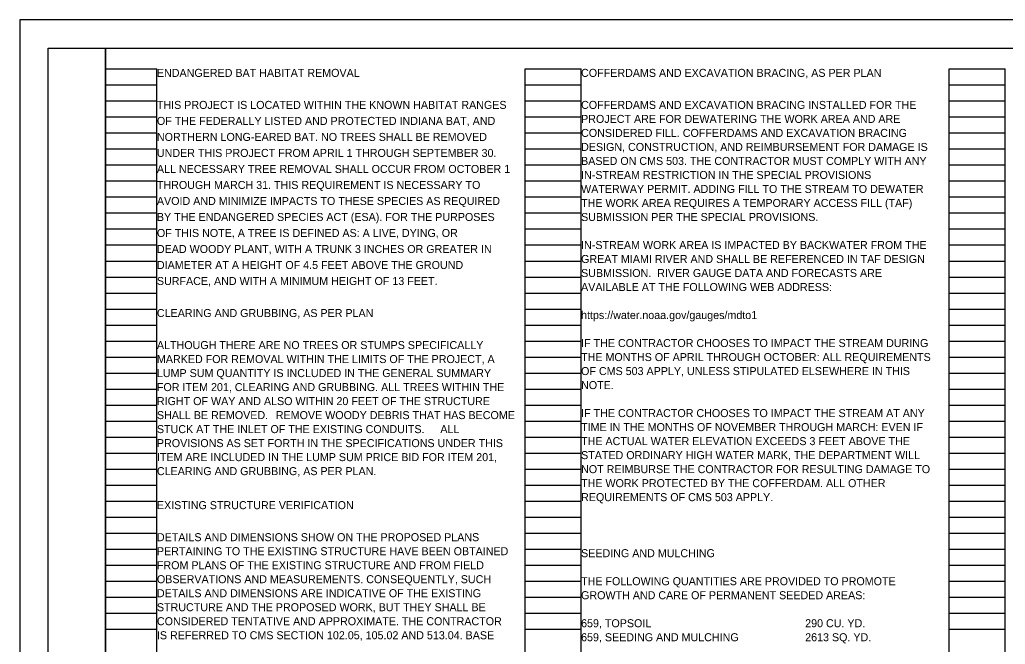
# Model space of a CAD drawing. Extents: x 0 to 34, y 0 to 41.9.
# Drawn here: x 0 to 17.24, y 11.08 to 22 of the extents above; entities that cross this region are included whole.
import ezdxf

# ---------------------------------------------------------------- set-up
doc = ezdxf.new("R2010")
doc.units = 0
for name, color, linetype in [('SH_Border', 7, 'Continuous'), ('SH_Cut_Line', 7, 'Continuous'), ('SH_Data', 7, 'Continuous'), ('SH_Text', 7, 'Continuous')]:
    doc.layers.add(name, color=color, linetype=linetype)

msp = doc.modelspace()

# ---------------------------------------------------------------- linework, layer by layer
at = {"layer": 'SH_Border'}
for points in [[(0.5, 21.5), (1.5, 21.5), (1.5, 0.5), (0.5, 0.5)], [(1.5, 21.5), (33.5, 21.5), (33.5, 0.5), (1.5, 0.5)]]:
    msp.add_lwpolyline(points, close=True, dxfattribs=at)
at = {"layer": 'SH_Cut_Line'}
msp.add_lwpolyline([(0, 0), (34, 0), (34, 22), (0, 22)], close=True, dxfattribs=at)
at = {"layer": 'SH_Data'}
for p, q in [((1.5, 0.98), (1.5, 21.14)), ((1.5, 21.14), (2.4, 21.14)), ((2.4, 0.98), (2.4, 21.14)), ((8.84, 0.98), (8.84, 21.14)), ((8.84, 21.14), (9.82, 21.14)), ((9.82, 0.98), (9.82, 21.14)), ((16.26, 0.98), (16.26, 21.14)), ((16.26, 21.14), (17.24, 21.14)), ((17.24, 0.98), (17.24, 21.14)), ((1.5, 20.86), (2.4, 20.86)), ((8.84, 20.86), (9.82, 20.86)), ((16.26, 20.86), (17.24, 20.86)), ((1.5, 20.58), (2.4, 20.58)), ((8.84, 20.58), (9.82, 20.58)), ((16.26, 20.58), (17.24, 20.58)), ((1.5, 20.3), (2.4, 20.3)), ((8.84, 20.3), (9.82, 20.3)), ((16.26, 20.3), (17.24, 20.3)), ((1.5, 20.02), (2.4, 20.02)), ((8.84, 20.02), (9.82, 20.02)), ((16.26, 20.02), (17.24, 20.02)), ((1.5, 19.74), (2.4, 19.74)), ((8.84, 19.74), (9.82, 19.74)), ((16.26, 19.74), (17.24, 19.74)), ((1.5, 19.46), (2.4, 19.46)), ((8.84, 19.46), (9.82, 19.46)), ((16.26, 19.46), (17.24, 19.46)), ((1.5, 19.18), (2.4, 19.18)), ((8.84, 19.18), (9.82, 19.18)), ((16.26, 19.18), (17.24, 19.18)), ((1.5, 18.9), (2.4, 18.9)), ((8.84, 18.9), (9.82, 18.9)), ((16.26, 18.9), (17.24, 18.9)), ((1.5, 18.62), (2.4, 18.62)), ((8.84, 18.62), (9.82, 18.62)), ((16.26, 18.62), (17.24, 18.62)), ((1.5, 18.34), (2.4, 18.34)), ((8.84, 18.34), (9.82, 18.34)), ((16.26, 18.34), (17.24, 18.34)), ((1.5, 18.06), (2.4, 18.06)), ((8.84, 18.06), (9.82, 18.06)), ((16.26, 18.06), (17.24, 18.06)), ((1.5, 17.78), (2.4, 17.78)), ((8.84, 17.78), (9.82, 17.78)), ((16.26, 17.78), (17.24, 17.78)), ((1.5, 17.5), (2.4, 17.5)), ((8.84, 17.5), (9.82, 17.5)), ((16.26, 17.5), (17.24, 17.5)), ((1.5, 17.22), (2.4, 17.22)), ((8.84, 17.22), (9.82, 17.22)), ((16.26, 17.22), (17.24, 17.22)), ((1.5, 16.94), (2.4, 16.94)), ((8.84, 16.94), (9.82, 16.94)), ((16.26, 16.94), (17.24, 16.94)), ((1.5, 16.66), (2.4, 16.66)), ((8.84, 16.66), (9.82, 16.66)), ((16.26, 16.66), (17.24, 16.66)), ((1.5, 16.38), (2.4, 16.38)), ((8.84, 16.38), (9.82, 16.38)), ((16.26, 16.38), (17.24, 16.38)), ((1.5, 16.1), (2.4, 16.1)), ((8.84, 16.1), (9.82, 16.1)), ((16.26, 16.1), (17.24, 16.1)), ((1.5, 15.82), (2.4, 15.82)), ((8.84, 15.82), (9.82, 15.82)), ((16.26, 15.82), (17.24, 15.82)), ((1.5, 15.54), (2.4, 15.54)), ((8.84, 15.54), (9.82, 15.54)), ((16.26, 15.54), (17.24, 15.54)), ((1.5, 15.26), (2.4, 15.26)), ((8.84, 15.26), (9.82, 15.26)), ((16.26, 15.26), (17.24, 15.26)), ((1.5, 14.98), (2.4, 14.98)), ((8.84, 14.98), (9.82, 14.98)), ((16.26, 14.98), (17.24, 14.98)), ((1.5, 14.7), (2.4, 14.7)), ((8.84, 14.7), (9.82, 14.7)), ((16.26, 14.7), (17.24, 14.7)), ((1.5, 14.42), (2.4, 14.42)), ((8.84, 14.42), (9.82, 14.42)), ((16.26, 14.42), (17.24, 14.42)), ((1.5, 14.14), (2.4, 14.14)), ((8.84, 14.14), (9.82, 14.14)), ((16.26, 14.14), (17.24, 14.14)), ((1.5, 13.86), (2.4, 13.86)), ((8.84, 13.86), (9.82, 13.86)), ((16.26, 13.86), (17.24, 13.86)), ((1.5, 13.58), (2.4, 13.58)), ((8.84, 13.58), (9.82, 13.58)), ((16.26, 13.58), (17.24, 13.58)), ((1.5, 13.3), (2.4, 13.3)), ((8.84, 13.3), (9.82, 13.3)), ((16.26, 13.3), (17.24, 13.3)), ((1.5, 13.02), (2.4, 13.02)), ((8.84, 13.02), (9.82, 13.02)), ((16.26, 13.02), (17.24, 13.02)), ((1.5, 12.74), (2.4, 12.74)), ((8.84, 12.74), (9.82, 12.74)), ((16.26, 12.74), (17.24, 12.74)), ((1.5, 12.46), (2.4, 12.46)), ((8.84, 12.46), (9.82, 12.46)), ((16.26, 12.46), (17.24, 12.46)), ((1.5, 12.18), (2.4, 12.18)), ((8.84, 12.18), (9.82, 12.18)), ((16.26, 12.18), (17.24, 12.18)), ((1.5, 11.9), (2.4, 11.9)), ((8.84, 11.9), (9.82, 11.9)), ((16.26, 11.9), (17.24, 11.9)), ((1.5, 11.62), (2.4, 11.62)), ((8.84, 11.62), (9.82, 11.62)), ((16.26, 11.62), (17.24, 11.62)), ((1.5, 11.34), (2.4, 11.34)), ((8.84, 11.34), (9.82, 11.34)), ((16.26, 11.34), (17.24, 11.34))]:
    msp.add_line(p, q, dxfattribs=at)

# ---------------------------------------------------------------- texts
at = {"layer": 'SH_Text'}
for s, p in [('ENDANGERED BAT HABITAT REMOVAL', (2.4, 21)), ('COFFERDAMS AND EXCAVATION BRACING, AS PER PLAN', (9.82, 21)), ('THIS PROJECT IS LOCATED WITHIN THE KNOWN HABITAT RANGES', (2.4, 20.44)), ('COFFERDAMS AND EXCAVATION BRACING INSTALLED FOR THE ', (9.82, 20.44)), ('OF THE FEDERALLY LISTED AND PROTECTED INDIANA BAT, AND', (2.4, 20.16)), ('PROJECT ARE FOR DEWATERING THE WORK AREA AND ARE ', (9.82, 20.195)), ('NORTHERN LONG-EARED BAT. NO TREES SHALL BE REMOVED', (2.4, 19.88)), ('CONSIDERED FILL. COFFERDAMS AND EXCAVATION BRACING ', (9.82, 19.95)), ('DESIGN, CONSTRUCTION, AND REIMBURSEMENT FOR DAMAGE IS ', (9.82, 19.705)), ('UNDER THIS PROJECT FROM APRIL 1 THROUGH SEPTEMBER 30.', (2.4, 19.6)), ('BASED ON CMS 503. THE CONTRACTOR MUST COMPLY WITH ANY ', (9.82, 19.46)), ('ALL NECESSARY TREE REMOVAL SHALL OCCUR FROM OCTOBER 1', (2.4, 19.32)), ('IN-STREAM RESTRICTION IN THE SPECIAL PROVISIONS  ', (9.82, 19.215)), ('THROUGH MARCH 31. THIS REQUIREMENT IS NECESSARY TO', (2.4, 19.04)), ('WATERWAY PERMIT. ADDING FILL TO THE STREAM TO DEWATER ', (9.82, 18.97)), ('AVOID AND MINIMIZE IMPACTS TO THESE SPECIES AS REQUIRED', (2.4, 18.76)), ('THE WORK AREA REQUIRES A TEMPORARY ACCESS FILL (TAF) ', (9.82, 18.725)), ('BY THE ENDANGERED SPECIES ACT (ESA). FOR THE PURPOSES', (2.4, 18.48)), ('SUBMISSION PER THE SPECIAL PROVISIONS. ', (9.82, 18.48)), ('OF THIS NOTE, A TREE IS DEFINED AS: A LIVE, DYING, OR', (2.4, 18.2)), ('IN-STREAM WORK AREA IS IMPACTED BY BACKWATER FROM THE ', (9.82, 17.99)), ('DEAD WOODY PLANT, WITH A TRUNK 3 INCHES OR GREATER IN', (2.4, 17.92)), ('DIAMETER AT A HEIGHT OF 4.5 FEET ABOVE THE GROUND', (2.4, 17.64)), ('GREAT MIAMI RIVER AND SHALL BE REFERENCED IN TAF DESIGN ', (9.82, 17.745)), ('SUBMISSION.  RIVER GAUGE DATA AND FORECASTS ARE ', (9.82, 17.5)), ('SURFACE, AND WITH A MINIMUM HEIGHT OF 13 FEET.', (2.4, 17.36)), ('AVAILABLE AT THE FOLLOWING WEB ADDRESS:', (9.82, 17.255)), ('CLEARING AND GRUBBING, AS PER PLAN', (2.4, 16.8)), ('https://water.noaa.gov/gauges/mdto1', (9.82, 16.765)), ('ALTHOUGH THERE ARE NO TREES OR STUMPS SPECIFICALLY ', (2.4, 16.24)), ('IF THE CONTRACTOR CHOOSES TO IMPACT THE STREAM DURING ', (9.82, 16.275)), ('MARKED FOR REMOVAL WITHIN THE LIMITS OF THE PROJECT, A ', (2.4, 15.995)), ('THE MONTHS OF APRIL THROUGH OCTOBER: ALL REQUIREMENTS ', (9.82, 16.03)), ('LUMP SUM QUANTITY IS INCLUDED IN THE GENERAL SUMMARY ', (2.4, 15.75)), ('OF CMS 503 APPLY, UNLESS STIPULATED ELSEWHERE IN THIS ', (9.82, 15.785)), ('FOR ITEM 201, CLEARING AND GRUBBING. ALL TREES WITHIN THE ', (2.4, 15.505)), ('NOTE.', (9.82, 15.54)), ('RIGHT OF WAY AND ALSO WITHIN 20 FEET OF THE STRUCTURE ', (2.4, 15.26)), ('IF THE CONTRACTOR CHOOSES TO IMPACT THE STREAM AT ANY ', (9.82, 15.05)), ('SHALL BE REMOVED. ', (2.4, 15.015)), ('REMOVE WOODY DEBRIS THAT HAS BECOME ', (4.48, 15.015)), ('STUCK AT THE INLET OF THE EXISTING CONDUITS. ', (2.4, 14.77)), (' ALL ', (7.306, 14.77)), ('TIME IN THE MONTHS OF NOVEMBER THROUGH MARCH: EVEN IF ', (9.82, 14.805)), ('PROVISIONS AS SET FORTH IN THE SPECIFICATIONS UNDER THIS ', (2.4, 14.525)), ('THE ACTUAL WATER ELEVATION EXCEEDS 3 FEET ABOVE THE ', (9.82, 14.56)), ('ITEM ARE INCLUDED IN THE LUMP SUM PRICE BID FOR ITEM 201, ', (2.4, 14.28)), ('STATED ORDINARY HIGH WATER MARK, THE DEPARTMENT WILL ', (9.82, 14.315)), ('CLEARING AND GRUBBING, AS PER PLAN.', (2.4, 14.035)), ('NOT REIMBURSE THE CONTRACTOR FOR RESULTING DAMAGE TO ', (9.82, 14.07)), ('THE WORK PROTECTED BY THE COFFERDAM. ALL OTHER ', (9.82, 13.825)), ('REQUIREMENTS OF CMS 503 APPLY.', (9.82, 13.58)), ('EXISTING STRUCTURE VERIFICATION', (2.4, 13.44)), ('DETAILS AND DIMENSIONS SHOW ON THE PROPOSED PLANS ', (2.4, 12.88)), ('PERTAINING TO THE EXISTING STRUCTURE HAVE BEEN OBTAINED ', (2.4, 12.635)), ('SEEDING AND MULCHING', (9.82, 12.6)), ('FROM PLANS OF THE EXISTING STRUCTURE AND FROM FIELD ', (2.4, 12.39)), ('OBSERVATIONS AND MEASUREMENTS. CONSEQUENTLY, SUCH ', (2.4, 12.145)), ('THE FOLLOWING QUANTITIES ARE PROVIDED TO PROMOTE', (9.82, 12.11)), ('DETAILS AND DIMENSIONS ARE INDICATIVE OF THE EXISTING ', (2.4, 11.9)), ('GROWTH AND CARE OF PERMANENT SEEDED AREAS:', (9.82, 11.865)), ('STRUCTURE AND THE PROPOSED WORK, BUT THEY SHALL BE ', (2.4, 11.655)), ('CONSIDERED TENTATIVE AND APPROXIMATE. THE CONTRACTOR ', (2.4, 11.41)), ('659, TOPSOIL', (9.82, 11.375)), ('290 CU. YD.', (13.74, 11.375)), ('IS REFERRED TO CMS SECTION 102.05, 105.02 AND 513.04. BASE ', (2.4, 11.165)), ('659, SEEDING AND MULCHING', (9.82, 11.13)), ('2613 SQ. YD.', (13.74, 11.13))]:
    msp.add_text(s, height=0.14, dxfattribs=at).set_placement(p)

doc.saveas('drawing.dxf')
